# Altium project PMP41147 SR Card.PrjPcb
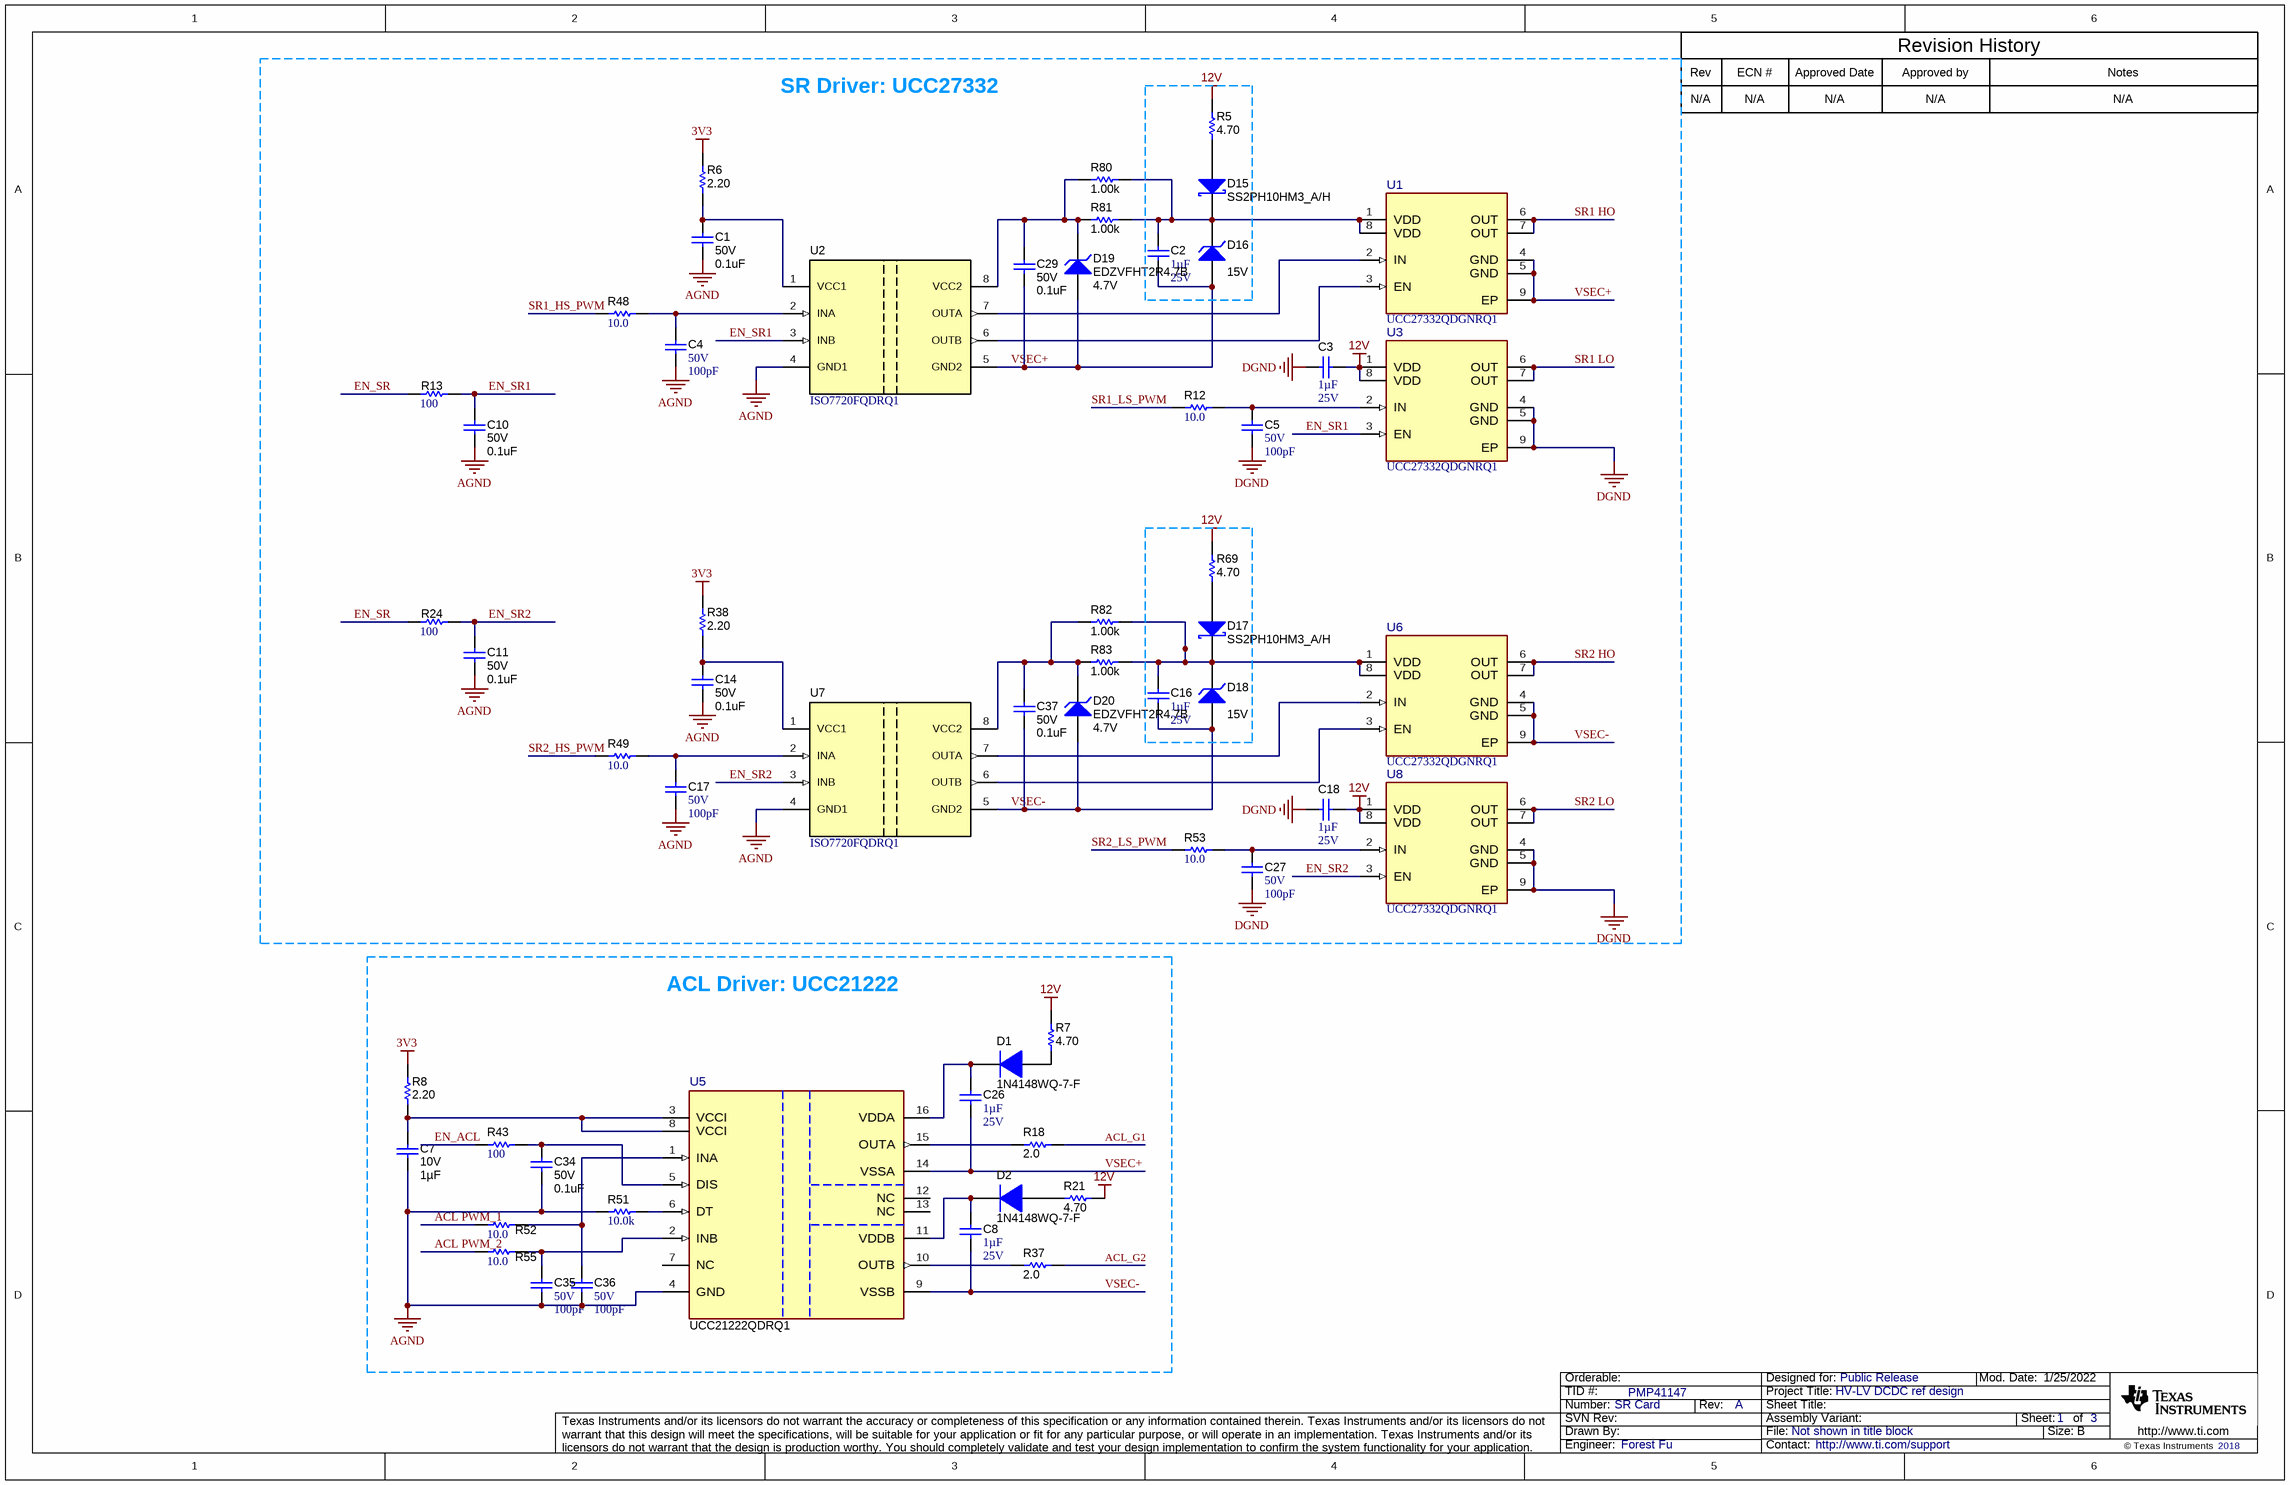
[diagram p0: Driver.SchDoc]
CopyrightYear: 2018; PCB_Layout: Forest Fu; PCB_Rev: A; PRJ_Customer: Public Release; PRJ_Engineer: Forest Fu; PRJ_Number: SR Card; PRJ_Title: HV-LV DCDC ref design; SCH_Rev: A; TechSupport: http://www.ti.com/support; TID: PMP41147
3 sheets, 165 parts. Net scope: global (net labels, ports and power ports of the same name join across sheets).
Board file: SR Card.PcbDoc
Sheets:
  Driver.SchDoc
  Power Stage.SchDoc
  SR Card_Hardware.SchDoc

## Sheet Driver.SchDoc
size 431 x 279 mm; Date: Not shown in title block; ApprovedBy: Not shown in title block; CheckedBy: Not shown in title block; Author: Not shown in title block; CompanyName: Not shown in title block; Engineer: Not shown in title block; Organization: Not shown in title block; Address1: Not shown in title block; Address2: Not shown in title block; Address3: Not shown in title block; Address4: Not shown in title block; DocumentNumber: 1; Revision: Use project parameter SCH_Rev; SheetNumber: 1; SheetTotal: 3; PageSetup: Record=PageOptions¦CenterHorizontal=True¦CenterVertical=True¦PrintScale=1.00¦XCorrection=1.00¦YCorrection=1.00¦PrintKind=0¦BorderSize=5000000¦LeftOffset=0¦BottomOffset=0¦Orientation=2¦PaperLength=1000¦PaperWidth=1000¦Scale=100¦PaperSource=15¦PrintQuality=600¦MediaType=1¦DitherType=10¦PaperKind=Letter¦PrintScaleMode=1

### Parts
C1  VDC_V: 50V  ValueDisplayed: 0.1uF  [0402]  (hidden comment: GCM155R71H104KE02D)
C2  Cap_F: 1µF  VDC_V: 25V  [0603]  (hidden comment: CGA3E1X7R1E105M080AC)
C3  Cap_F: 1µF  VDC_V: 25V  [0603]  (hidden comment: CGA3E1X7R1E105M080AC)
C4  VDC_V: 50V  ValueDisplayed: 100pF  [0402]  (hidden comment: CC0402KRX7R9BB101)
C5  VDC_V: 50V  ValueDisplayed: 100pF  [0402]  (hidden comment: CC0402KRX7R9BB101)
C7  VDC_V: 10V  ValueDisplayed: 1µF  [0402]  (hidden comment: GRT155C71A105KE13D)
C8  Cap_F: 1µF  VDC_V: 25V  [0603]  (hidden comment: CGA3E1X7R1E105M080AC)
C10  VDC_V: 50V  ValueDisplayed: 0.1uF  [0402]  (hidden comment: GCM155R71H104KE02D)
C11  VDC_V: 50V  ValueDisplayed: 0.1uF  [0402]  (hidden comment: GCM155R71H104KE02D)
C14  VDC_V: 50V  ValueDisplayed: 0.1uF  [0402]  (hidden comment: GCM155R71H104KE02D)
C16  Cap_F: 1µF  VDC_V: 25V  [0603]  (hidden comment: CGA3E1X7R1E105M080AC)
C17  VDC_V: 50V  ValueDisplayed: 100pF  [0402]  (hidden comment: CC0402KRX7R9BB101)
C18  Cap_F: 1µF  VDC_V: 25V  [0603]  (hidden comment: CGA3E1X7R1E105M080AC)
C26  Cap_F: 1µF  VDC_V: 25V  [0603]  (hidden comment: CGA3E1X7R1E105M080AC)
C27  VDC_V: 50V  ValueDisplayed: 100pF  [0402]  (hidden comment: CC0402KRX7R9BB101)
C29  VDC_V: 50V  ValueDisplayed: 0.1uF  [0402]  (hidden comment: GCM155R71H104KE02D)
C34  VDC_V: 50V  ValueDisplayed: 0.1uF  [0402]  (hidden comment: GCM155R71H104KE02D)
C35  VDC_V: 50V  ValueDisplayed: 100pF  [0402]  (hidden comment: CC0402KRX7R9BB101)
C36  VDC_V: 50V  ValueDisplayed: 100pF  [0402]  (hidden comment: CC0402KRX7R9BB101)
C37  VDC_V: 50V  ValueDisplayed: 0.1uF  [0402]  (hidden comment: GCM155R71H104KE02D)
D1  1N4148WQ-7-F  [SOD-123]
D2  1N4148WQ-7-F  [SOD-123]
D15  SS2PH10HM3_A/H  [DO-220AA]
D16  value 15V  [SOD-323]  (hidden comment: SZMM3Z15VST1G)
D17  SS2PH10HM3_A/H  [DO-220AA]
D18  value 15V  [SOD-323]  (hidden comment: SZMM3Z15VST1G)
D19  EDZVFHT2R4.7B  value 4.7V  [SOD-523]
D20  EDZVFHT2R4.7B  value 4.7V  [SOD-523]
R5  ValueDisplayed: 4.70  [0805_HV]  (hidden comment: CRCW08054R70FKEAHP)
R6  ValueDisplayed: 2.20  [0402]  (hidden comment: RL0510S-2R2-F)
R7  ValueDisplayed: 4.70  [0805_HV]  (hidden comment: CRCW08054R70FKEAHP)
R8  ValueDisplayed: 2.20  [0402]  (hidden comment: RL0510S-2R2-F)
R12  ValueDisplayed: 10.0  [0402]  (hidden comment: RMCF0402JT10R0)
R13  ValueDisplayed: 100  [0402]  (hidden comment: CRCW0402100RFKED)
R18  ValueDisplayed: 2.0  [0603]  (hidden comment: CRCW06032R00JNEA)
R21  ValueDisplayed: 4.70  [0805_HV]  (hidden comment: CRCW08054R70FKEAHP)
R24  ValueDisplayed: 100  [0402]  (hidden comment: CRCW0402100RFKED)
R37  ValueDisplayed: 2.0  [0603]  (hidden comment: CRCW06032R00JNEA)
R38  ValueDisplayed: 2.20  [0402]  (hidden comment: RL0510S-2R2-F)
R43  ValueDisplayed: 100  [0402]  (hidden comment: CRCW0402100RFKED)
R48  ValueDisplayed: 10.0  [0402]  (hidden comment: RMCF0402JT10R0)
R49  ValueDisplayed: 10.0  [0402]  (hidden comment: RMCF0402JT10R0)
R51  ValueDisplayed: 10.0k  [0402]  (hidden comment: ERJPA2F1002X)
R52  ValueDisplayed: 10.0  [0402]  (hidden comment: RMCF0402JT10R0)
R53  ValueDisplayed: 10.0  [0402]  (hidden comment: RMCF0402JT10R0)
R55  ValueDisplayed: 10.0  [0402]  (hidden comment: RMCF0402JT10R0)
R69  ValueDisplayed: 4.70  [0805_HV]  (hidden comment: CRCW08054R70FKEAHP)
R80  ValueDisplayed: 1.00k  [0402]  (hidden comment: ERA-2APB102X)
R81  ValueDisplayed: 1.00k  [0402]  (hidden comment: ERA-2APB102X)
R82  ValueDisplayed: 1.00k  [0402]  (hidden comment: ERA-2APB102X)
R83  ValueDisplayed: 1.00k  [0402]  (hidden comment: ERA-2APB102X)
U1  UCC27332QDGNRQ1  [DGN0008G-MFG]
U2  ISO7720FQDRQ1  [D0008A_N]
U3  UCC27332QDGNRQ1  [DGN0008G-MFG]
U5  UCC21222QDRQ1  [D0016B-MFG]
U6  UCC27332QDGNRQ1  [DGN0008G-MFG]
U7  ISO7720FQDRQ1  [D0008A_N]
U8  UCC27332QDGNRQ1  [DGN0008G-MFG]

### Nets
3V3: R6.2 R8.2 R38.2
12V: C3.1 C18.1 R5.2 R7.2 R21.1 R69.2 U3.1(VDD) U3.8(VDD) U8.1(VDD) U8.8(VDD)
AGND: C1.2 C4.1 C7.2 C10.2 C11.2 C14.2 C17.1 C34.2 C35.2 C36.2 R51.2 U2.4(GND1) U5.4(GND) U7.4(GND1)
DGND: C3.2 C5.2 C18.2 C27.2 U3.4(GND) U3.5(GND) U3.9(EP) U8.4(GND) U8.5(GND) U8.9(EP)
ACL PWM_1: R52.1
ACL PWM_2: R55.1
ACL_G1: R18.2
ACL_G2: R37.2
EN_ACL: R43.1
EN_SR: R13.1 R24.1
EN_SR1: C10.1 R13.2 U2.3(INB) U3.3(EN)
EN_SR2: C11.1 R24.2 U7.3(INB) U8.3(EN)
SR1 HO: U1.6(OUT) U1.7(OUT)
SR1 LO: U3.6(OUT) U3.7(OUT)
SR1_HS_PWM: R48.1
SR1_LS_PWM: R12.1
SR2 HO: U6.6(OUT) U6.7(OUT)
SR2 LO: U8.6(OUT) U8.7(OUT)
SR2_HS_PWM: R49.1
SR2_LS_PWM: R53.1
VSEC+: C2.2 C26.2 C29.2 D16.2(A) D19.2(A) U1.4(GND) U1.5(GND) U1.9(EP) U2.5(GND2) U5.14(VSSA)
VSEC-: C8.2 C16.2 C37.2 D18.2(A) D20.2(A) U5.9(VSSB) U6.4(GND) U6.5(GND) U6.9(EP) U7.5(GND2)
NetC1_1: C1.1 R6.1 U2.1(VCC1)
NetC2_1: C2.1 D15.1(K) D16.1(K) R80.2 R81.2 U1.1(VDD) U1.8(VDD)
NetC4_2: C4.2 R48.2 U2.2(INA)
NetC5_1: C5.1 R12.2 U3.2(IN)
NetC7_1: C7.1 R8.1 U5.3(VCCI) U5.8(VCCI)
NetC8_1: C8.1 D2.1(K) U5.11(VDDB)
NetC14_1: C14.1 R38.1 U7.1(VCC1)
NetC16_1: C16.1 D17.1(K) D18.1(K) R82.2 R83.2 U6.1(VDD) U6.8(VDD)
NetC17_2: C17.2 R49.2 U7.2(INA)
NetC26_1: C26.1 D1.1(K) U5.16(VDDA)
NetC27_1: C27.1 R53.2 U8.2(IN)
NetC29_1: C29.1 D19.1(K) R80.1 R81.1 U2.8(VCC2)
NetC34_1: C34.1 R43.2 U5.5(DIS)
NetC35_1: C35.1 R55.2 U5.2(INB)
NetC36_1: C36.1 R52.2 U5.1(INA)
NetC37_1: C37.1 D20.1(K) R82.1 R83.1 U7.8(VCC2)
NetD1_2: D1.2(A) R7.1
NetD2_2: D2.2(A) R21.2
NetD15_2: D15.2(A) R5.1
NetD17_2: D17.2(A) R69.1
NetR18_1: R18.1 U5.15(OUTA)
NetR37_1: R37.1 U5.10(OUTB)
NetR51_1: R51.1 U5.6(DT)
NetU1_2: U1.2(IN) U2.7(OUTA)
NetU1_3: U1.3(EN) U2.6(OUTB)
NetU6_2: U6.2(IN) U7.7(OUTA)
NetU6_3: U6.3(EN) U7.6(OUTB)

Not connected (* = marked no-connect by the designer): U5 7(NC) 12(NC) 13(NC)

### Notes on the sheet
- SR Driver: UCC27332
- Rev
- N/A
- ECN #
- Approved Date
- Approved by
- Revision History
- Notes
- ACL Driver: UCC21222

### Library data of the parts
C1 C10 C11 C14 C29 C34 C37 = CMP-0006356-1: CAP, CERM, 0.1 uF, 50 V, +/- 10%, X7R, AEC-Q200 Grade 1, 0402; Manufacturer: MuRata; TaMin_C: -55°C; Polarized: N; SizeAreaWB_mm2: 3; Value1: Unknown; U/M: EA; Value: 0.1uF; TaMax_C: 125°C; SizeZ_mm: 0.6; SizeX_mm: 1; SizeY_mm: 0.5; AEC Qualified: Y; Cap_F: 100nF; AEC Category: Q200
C2 C3 C8 C16 C18 C26 = CMP-0082113-1: CAP, CERM, 1 µF, 25 V,+/- 20%, X7R, AEC-Q200 Grade 1, 0603; Manufacturer: TDK; SizeAreaWB_mm2: 4.68; SizeArea_mm2: 1.28; AEC Qualified: Y; AEC Category: Q200; Value: 1uF; TaMax_C: 125°C; SizeZ_mm: 1; Polarized: N; TaMin_C: -55°C; SizeY_mm: 0.8; U/M: EA; SizeX_mm: 1.6
C4 C5 C17 C27 C35 C36 = CMP-0006305-2: CAP, CERM, 100 pF, 50 V, +/- 10%, X7R, 0402; Manufacturer: Yageo America; TaMin_C: -55°C; Polarized: N; SizeAreaWB_mm2: 3; Value1: Unknown; U/M: EA; Value: 100pF; TaMax_C: 125°C; SizeZ_mm: 0.6; SizeX_mm: 1; SizeY_mm: 0.5; AEC Category: Q200
C7 = CMP-0085818-1: CAP, CERM, 1 µF, 10 V,+/- 10%, X7S, AEC-Q200 Grade 1, 0402; Manufacturer: MuRata; Value: 1uF; SizeX_mm: 1; TaMax_C: 125°C; SizeArea_mm2: 0.5; SizeZ_mm: 0.6; AEC Category: Q200; Polarized: N; SizeAreaWB_mm2: 3; TaMin_C: -55°C; AEC Qualified: Y; U/M: EA
D1 D2 = CMP-0750148-1: Diode, Switching, 100 V, 0.3 A, AEC-Q101, SOD-123; Manufacturer: Diodes Inc.; Value2: 1.25V; TJmax_C: 150°C; AEC Category: Q101; Value: 100V; SizeAreaWB_mm2: 13.095; SizeArea_mm2: 6.545; SizeX_mm: 3.85; AEC Qualified: Y; Io_A: 300mA; Value1: 0.3A; SizeZ_mm: 1.35; SizeY_mm: 1.7
D15 D17 = CMP-0028941-1: Diode, Schottky, 100 V, 2 A, AEC-Q101, DO-220AA; Manufacturer: Vishay-Semiconductor; Io_A: 2A; Green_Lifecycle: Not Set; SizeAreaWB_mm2: 14.3925; Vr_V: 100V; Green_REACh: Incomplete; TJmax_C: 175°C; U/M: EA; Value: 100V; SizeZ_mm: 1.15; SizeX_mm: 3.75; SizeY_mm: 2.03; Vf_V: 770mV; Value2: 0.77V; SizeArea_mm2: 7.6125; AEC Qualified: Y; AEC Category: Q101
D16 D18 = CMP-0085761-1: Diode, Zener, 15 V, 300 mW, AEC-Q101, SOD-323; Manufacturer: ON Semiconductor; Value1: 0.3W; Power_W: 300mW; SizeAreaWB_mm2: 8.695; AEC Category: Q101; SizeArea_mm2: 3.645; RJA_CperW: 416; SizeY_mm: 1.35; SizeX_mm: 2.7; AEC Qualified: Y; SizeZ_mm: 1
D19 D20 = CMP-0005910-2: Diode, Zener, 4.7 V, 150 mW, AEC-Q101, SOD-523; Manufacturer: Rohm; Power_W: 150mW; SizeAreaWB_mm2: 5.13; Value1: 0.15W; U/M: EA; SizeZ_mm: 0.65; SizeX_mm: 1.7; SizeY_mm: 0.9; SizeArea_mm2: 1.53; AEC Qualified: Y; AEC Category: Q101
R5 R7 R21 R69 = CMP-0021312-3: RES, 4.70, 1%, 0.5 W, AEC-Q200 Grade 0, 0805; Manufacturer: Vishay-Dale; Power_W: 500mW; TempCo: 100 ppm/C; Value_Code: 4R70; Value: 4.70; Res_ohm: 4.7; SizeX_mm: 2; SizeY_mm: 1.25; SizeZ_mm: 1.45; Value2: 0.5W; SizeArea_mm2: 2.5; AEC Qualified: Y; AEC Grade: 0; AEC Category: Q200; VDC_V: 150V
R6 R8 R38 = CMP-0082064-1: RES, 2.20, 1%, 0.167 W, AEC-Q200 Grade 0, 0402; Manufacturer: Susumu Co Ltd; Value_Code: 2R20; SizeAreaWB_mm2: 3; SizeArea_mm2: 0.5; AEC Qualified: Y; AEC Category: Q200; Res_ohm: 2.2; Value: 2.20; SizeZ_mm: 0.6; TempCo: 200 ppm/C; AEC Grade: 0; Power_W: 167mW; Value2: 0.167W; SizeX_mm: 1
R12 R48 R49 R52 R53 R55 = CMP-0026764-1: RES, 10.0, 1%, 0.063 W, AEC-Q200 Grade 0, 0402; Manufacturer: Stackpole Electronics Inc; Power_W: 63mW; TempCo: 100 ppm/C; Value_Code: 10R0; U/M: EA; Value: 10.0; EIA_Code: E96; Res_ohm: 10; SizeX_mm: 1; SizeY_mm: 0.5; SizeZ_mm: 0.6; Value2: 0.063W; AEC Qualified: Y; AEC Grade: 0; AEC Category: Q200
R13 R24 R43 = CMP-0025951-3: RES, 100, 1%, 0.063 W, AEC-Q200 Grade 0, 0402; Manufacturer: Vishay-Dale; Power_W: 63mW; TempCo: 100 ppm/C; Value_Code: 100R; Value: 100; EIA_Code: E96; SizeX_mm: 1; SizeY_mm: 0.5; SizeZ_mm: 0.6; Value2: 0.063W; AEC Qualified: Y; VDC_V: 50V; AEC Category: Q200; AEC Grade: 0
R18 R37 = CMP-0025776-4: RES, 2.0, 5%, 0.1 W, AEC-Q200 Grade 0, 0603; Manufacturer: Vishay-Dale; Power_W: 100mW; TempCo: 200 ppm/C; Value_Code: 2R00; Value: 2.0; EIA_Code: E24; Res_ohm: 2; SizeX_mm: 1.6; SizeY_mm: 0.8; SizeZ_mm: 1; Value2: 0.1W; SizeArea_mm2: 1.28; AEC Qualified: Y; VDC_V: 75V; AEC Category: Q200; AEC Grade: 0
R51 = CMP-0078779-1: RES, 10.0 k, 1%, 0.2 W, AEC-Q200 Grade 0, 0402; Manufacturer: Panasonic; Value_Code: 10k0; SizeArea_mm2: 0.5; AEC Qualified: Y; AEC Category: Q200; Res_ohm: 10k; Value: 10.0k; SizeZ_mm: 0.6; EIA_Code: E96; TempCo: 100 ppm/C; AEC Grade: 0; Power_W: 200mW; VDC_V: 50V; Value2: 0.2W; SizeX_mm: 1
R80-R83 = CMP-0026790-1: RES, 1.00 k, 0.1%, 0.063 W, AEC-Q200 Grade 0, 0402; Manufacturer: Panasonic; Power_W: 63mW; TempCo: 15 ppm/C; Value_Code: 1k00; U/M: EA; Value: 1.00k; EIA_Code: E192; Res_ohm: 1k; SizeX_mm: 1; SizeY_mm: 0.5; SizeZ_mm: 0.6; Value2: 0.063W; AEC Qualified: Y; VDC_V: 50V; AEC Grade: 0; AEC Category: Q200
U1 U3 U6 U8 = CMP-0095529-1: Single 9-A High Speed Low-Side MOSFET Driver W Enable; Manufacturer: Texas Instruments; SizeZ_mm: 1.1mm; Number Of Outputs: 1; AEC Qualified: Unknown; Min Supply Voltage: 4V; Max Supply Voltage: 18V; Standoff Height: 0.05mm
U2 U7 = CMP-0860111-1: Automotive, High Speed, Robust EMC Reinforced Dual-Channel Digital Isolator, D0008A (SOIC-8); Manufacturer: Texas Instruments; SizeZ_mm: 1.75; CompType: IC; SizeArea_mm2: 30.38; SizeAreaWB_mm2: 56.58; AEC Qualified: Y; SizeX_mm: 4.9; SizeY_mm: 6.2; AEC Category: Q200
U5 = CMP-0090594-2: Half-Bridge Gate Driver IC CMOS/TTL 16-SOIC; Manufacturer: Texas Instruments; TaMin_C: -40°C; AEC Category: Q200; Turn On Delay Time: 28ns; Nominal Supply Current: 1-2.5mA; Max Power Dissipation: 1825mW; TJmax_C: +150°C; SizeZ_mm: 1.75mm; TaMax_C: +125°C; Fall Time: 6ns; Output Voltage: 9.2-18V; Standoff Height: 0.1mm; AEC Qualified: Yes; Rise Time: 5ns; Max Supply Voltage: 5.5V; Number Of Outputs: 2; AEC Grade: Grade 1; Propagation Delay: 25ns; Min Supply Voltage: 3V

## Sheet Power Stage.SchDoc
size 431 x 279 mm; Date: Not shown in title block; ApprovedBy: Not shown in title block; CheckedBy: Not shown in title block; Author: Not shown in title block; CompanyName: Not shown in title block; Engineer: Not shown in title block; Organization: Not shown in title block; Address1: Not shown in title block; Address2: Not shown in title block; Address3: Not shown in title block; Address4: Not shown in title block; DocumentNumber: 2; Revision: Use project parameter SCH_Rev; SheetNumber: 2; SheetTotal: 3; PageSetup: Record=PageOptions¦CenterHorizontal=True¦CenterVertical=True¦PrintScale=1.00¦XCorrection=1.00¦YCorrection=1.00¦PrintKind=0¦BorderSize=5000000¦LeftOffset=0¦BottomOffset=0¦Orientation=2¦PaperLength=1000¦PaperWidth=1000¦Scale=100¦PaperSource=15¦PrintQuality=600¦MediaType=1¦DitherType=10¦PaperKind=Letter¦PrintScaleMode=1
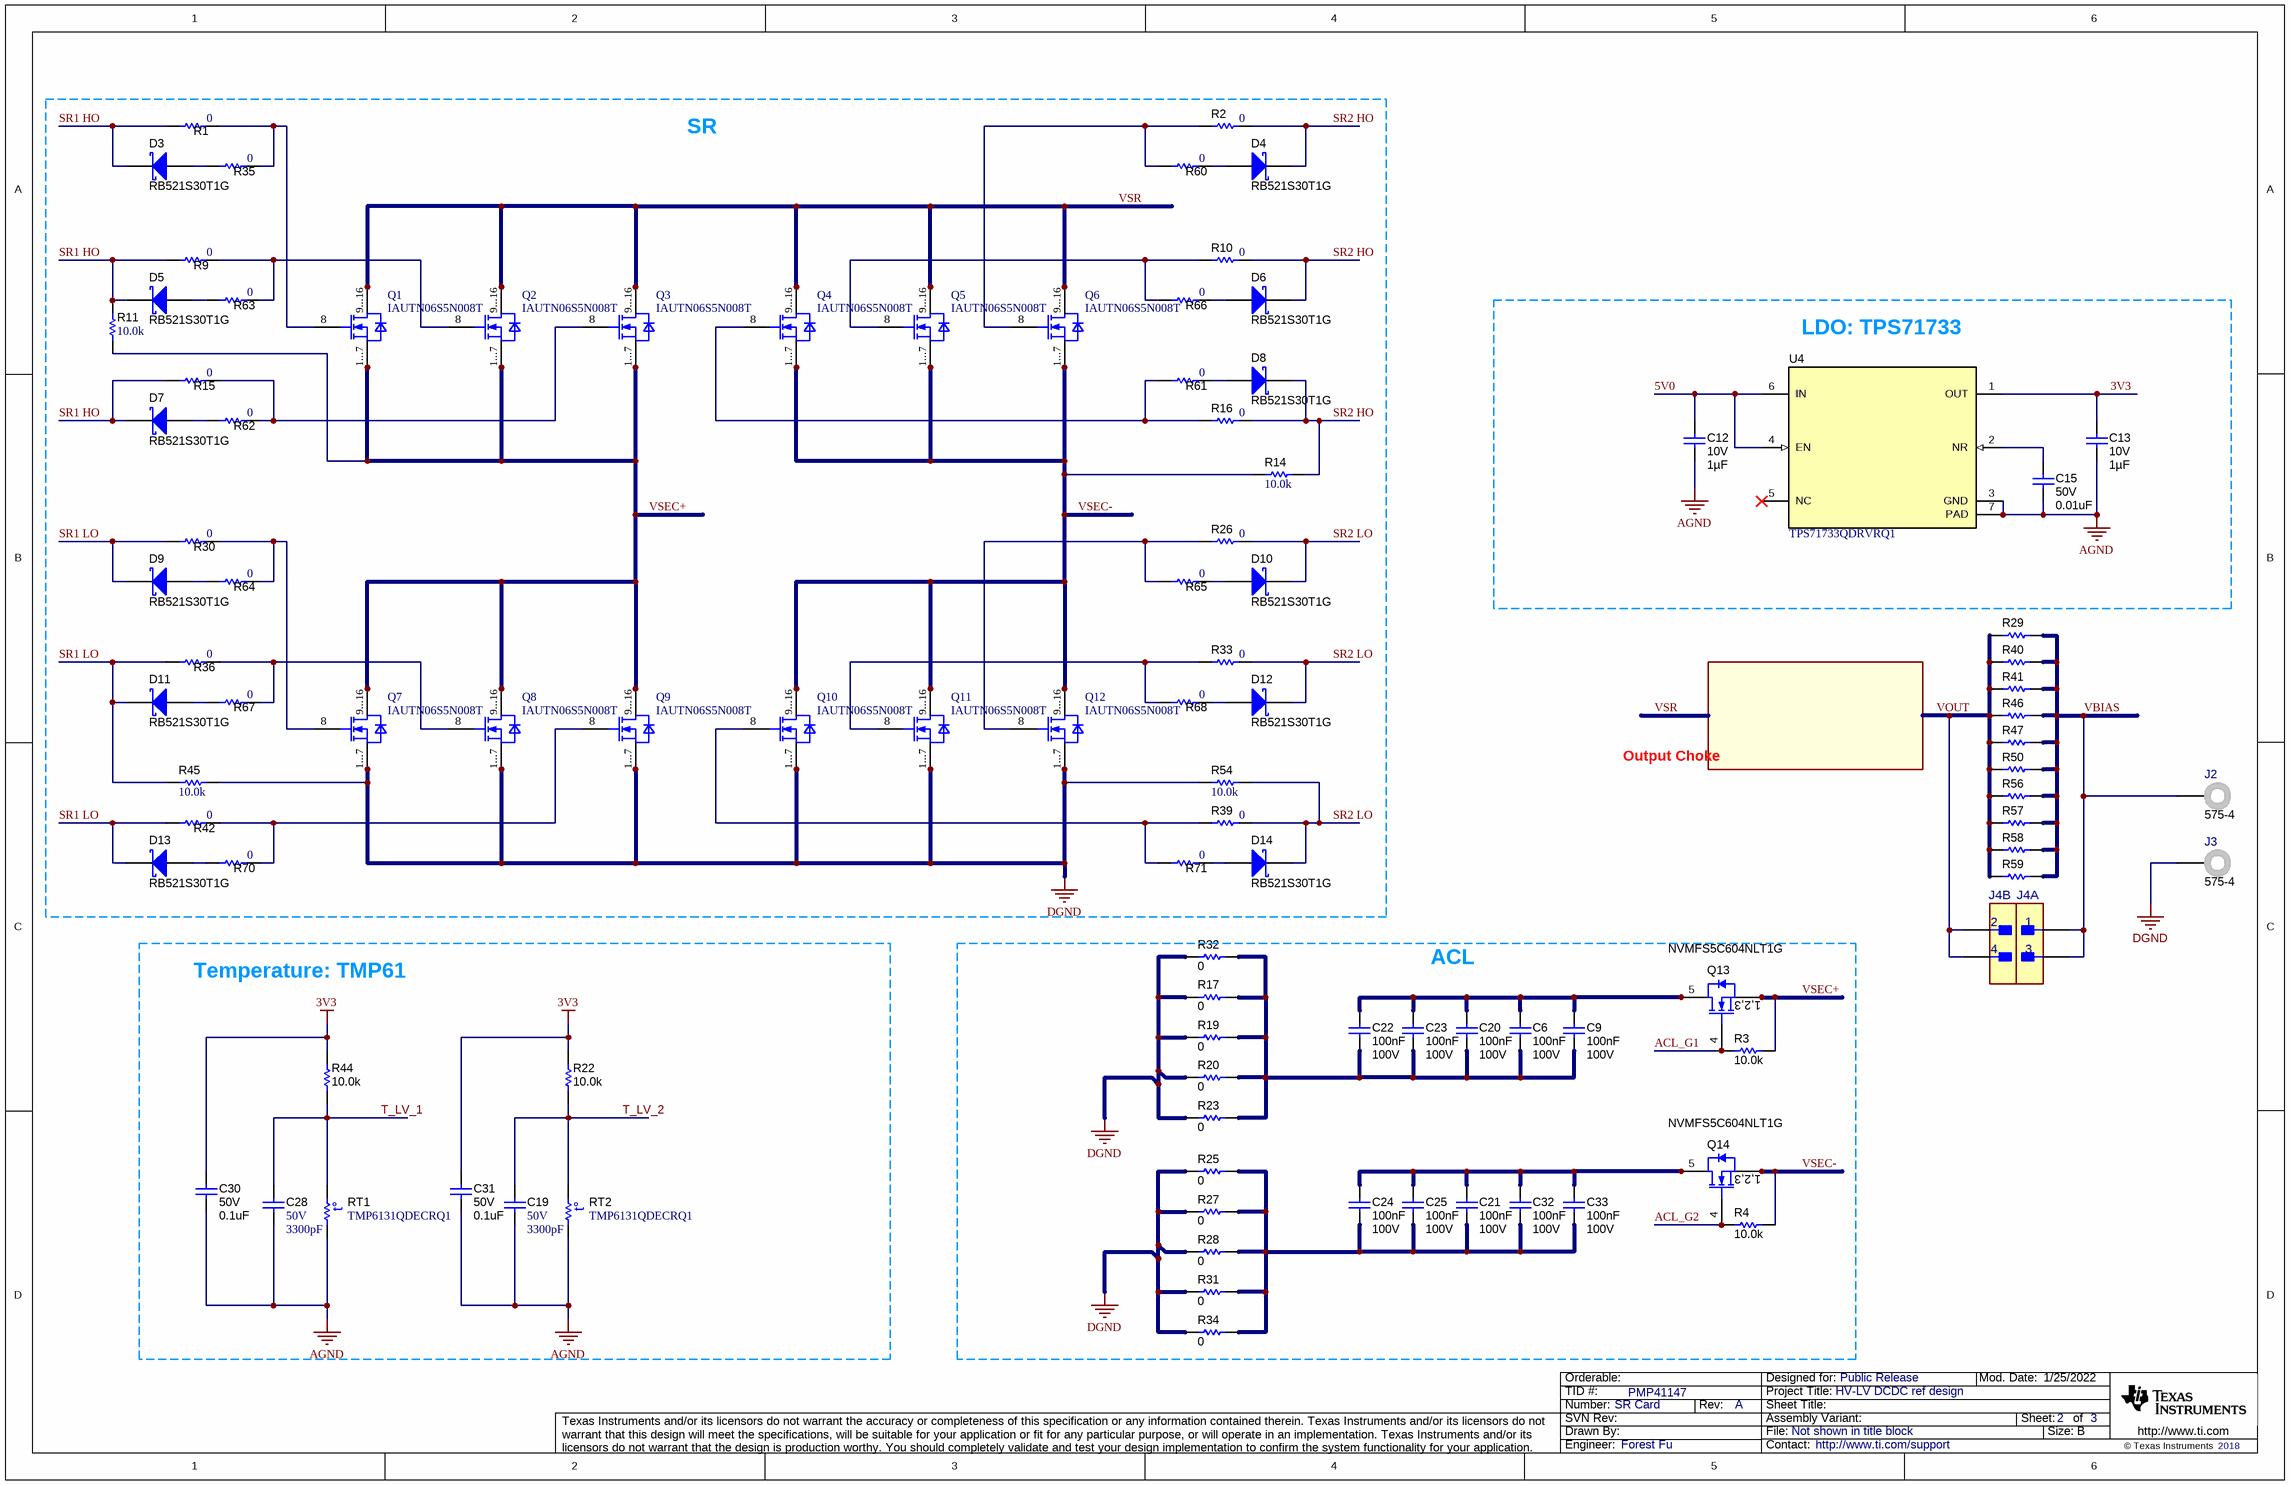
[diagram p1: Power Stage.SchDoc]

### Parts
C6  Cap_F: 100nF  VDC_V: 100V  [0805_HV]  (hidden comment: GCM21BR72A104KA37L)
C9  Cap_F: 100nF  VDC_V: 100V  [0805_HV]  (hidden comment: GCM21BR72A104KA37L)
C12  VDC_V: 10V  ValueDisplayed: 1µF  [0402]  (hidden comment: GRT155C71A105KE13D)
C13  VDC_V: 10V  ValueDisplayed: 1µF  [0402]  (hidden comment: GRT155C71A105KE13D)
C15  VDC_V: 50V  ValueDisplayed: 0.01uF  [0402]  (hidden comment: CGA2B3X7R1H103K050BB)
C19  VDC_V: 50V  ValueDisplayed: 3300pF  [0402]  (hidden comment: CGA2B2X7R1H332K050BA)
C20  Cap_F: 100nF  VDC_V: 100V  [0805_HV]  (hidden comment: GCM21BR72A104KA37L)
C21  Cap_F: 100nF  VDC_V: 100V  [0805_HV]  (hidden comment: GCM21BR72A104KA37L)
C22  Cap_F: 100nF  VDC_V: 100V  [0805_HV]  (hidden comment: GCM21BR72A104KA37L)
C23  Cap_F: 100nF  VDC_V: 100V  [0805_HV]  (hidden comment: GCM21BR72A104KA37L)
C24  Cap_F: 100nF  VDC_V: 100V  [0805_HV]  (hidden comment: GCM21BR72A104KA37L)
C25  Cap_F: 100nF  VDC_V: 100V  [0805_HV]  (hidden comment: GCM21BR72A104KA37L)
C28  VDC_V: 50V  ValueDisplayed: 3300pF  [0402]  (hidden comment: CGA2B2X7R1H332K050BA)
C30  VDC_V: 50V  ValueDisplayed: 0.1uF  [0402]  (hidden comment: GCM155R71H104KE02D)
C31  VDC_V: 50V  ValueDisplayed: 0.1uF  [0402]  (hidden comment: GCM155R71H104KE02D)
C32  Cap_F: 100nF  VDC_V: 100V  [0805_HV]  (hidden comment: GCM21BR72A104KA37L)
C33  Cap_F: 100nF  VDC_V: 100V  [0805_HV]  (hidden comment: GCM21BR72A104KA37L)
D3  RB521S30T1G  [SOD-523]
D4  RB521S30T1G  [SOD-523]
D5  RB521S30T1G  [SOD-523]
D6  RB521S30T1G  [SOD-523]
D7  RB521S30T1G  [SOD-523]
D8  RB521S30T1G  [SOD-523]
D9  RB521S30T1G  [SOD-523]
D10  RB521S30T1G  [SOD-523]
D11  RB521S30T1G  [SOD-523]
D12  RB521S30T1G  [SOD-523]
D13  RB521S30T1G  [SOD-523]
D14  RB521S30T1G  [SOD-523]
J2  575-4  [Keystone_575-4]
J3  575-4  [Keystone_575-4]
J4  FTSH-102-01-L-D-RA  [FP-FTSH-102-01-L-D-RA_HDR4-MFG]  (value not drawn)  (parts A,B of 2)
Q1  IAUTN06S5N008T  [SOIC120P1500X235-16N-1-V]
Q2  IAUTN06S5N008T  [SOIC120P1500X235-16N-1-V]
Q3  IAUTN06S5N008T  [SOIC120P1500X235-16N-1-V]
Q4  IAUTN06S5N008T  [SOIC120P1500X235-16N-1-V]
Q5  IAUTN06S5N008T  [SOIC120P1500X235-16N-1-V]
Q6  IAUTN06S5N008T  [SOIC120P1500X235-16N-1-V]
Q7  IAUTN06S5N008T  [SOIC120P1500X235-16N-1-V]
Q8  IAUTN06S5N008T  [SOIC120P1500X235-16N-1-V]
Q9  IAUTN06S5N008T  [SOIC120P1500X235-16N-1-V]
Q10  IAUTN06S5N008T  [SOIC120P1500X235-16N-1-V]
Q11  IAUTN06S5N008T  [SOIC120P1500X235-16N-1-V]
Q12  IAUTN06S5N008T  [SOIC120P1500X235-16N-1-V]
Q13  NVMFS5C604NLT1G  [TRANS_DFN5]
Q14  NVMFS5C604NLT1G  [TRANS_DFN5]
R1  ValueDisplayed: 0  [0402]  (hidden comment: CRCW04020000Z0EDHP)
R2  ValueDisplayed: 0  [0402]  (hidden comment: CRCW04020000Z0EDHP)
R3  ValueDisplayed: 10.0k  [0402]  (hidden comment: RMCF0402FT10K0)
R4  ValueDisplayed: 10.0k  [0402]  (hidden comment: RMCF0402FT10K0)
R9  ValueDisplayed: 0  [0402]  (hidden comment: CRCW04020000Z0EDHP)
R10  ValueDisplayed: 0  [0402]  (hidden comment: CRCW04020000Z0EDHP)
R11  ValueDisplayed: 10.0k  [0402]  (hidden comment: ERJPA2F1002X)
R14  ValueDisplayed: 10.0k  [0402]  (hidden comment: ERJPA2F1002X)
R15  ValueDisplayed: 0  [0402]  (hidden comment: CRCW04020000Z0EDHP)
R16  ValueDisplayed: 0  [0402]  (hidden comment: CRCW04020000Z0EDHP)
R17  ValueDisplayed: 0  [0805_HV]  (hidden comment: CRCW08050000Z0EA)
R19  ValueDisplayed: 0  [0805_HV]  (hidden comment: CRCW08050000Z0EA)
R20  ValueDisplayed: 0  [0805_HV]  (hidden comment: CRCW08050000Z0EA)
R22  ValueDisplayed: 10.0k  [0402]  (hidden comment: RMCF0402FT10K0)
R23  ValueDisplayed: 0  [0805_HV]  (hidden comment: CRCW08050000Z0EA)
R25  ValueDisplayed: 0  [0805_HV]  (hidden comment: CRCW08050000Z0EA)
R26  ValueDisplayed: 0  [0402]  (hidden comment: CRCW04020000Z0EDHP)
R27  ValueDisplayed: 0  [0805_HV]  (hidden comment: CRCW08050000Z0EA)
R28  ValueDisplayed: 0  [0805_HV]  (hidden comment: CRCW08050000Z0EA)
R29  LR12FTDR0M50  [2512]  (value not drawn)
R30  ValueDisplayed: 0  [0402]  (hidden comment: CRCW04020000Z0EDHP)
R31  ValueDisplayed: 0  [0805_HV]  (hidden comment: CRCW08050000Z0EA)
R32  ValueDisplayed: 0  [0805_HV]  (hidden comment: CRCW08050000Z0EA)
R33  ValueDisplayed: 0  [0402]  (hidden comment: CRCW04020000Z0EDHP)
R34  ValueDisplayed: 0  [0805_HV]  (hidden comment: CRCW08050000Z0EA)
R35  ValueDisplayed: 0  [0402]  (hidden comment: CRCW04020000Z0EDHP)
R36  ValueDisplayed: 0  [0402]  (hidden comment: CRCW04020000Z0EDHP)
R39  ValueDisplayed: 0  [0402]  (hidden comment: CRCW04020000Z0EDHP)
R40  LR12FTDR0M50  [2512]  (value not drawn)
R41  LR12FTDR0M50  [2512]  (value not drawn)
R42  ValueDisplayed: 0  [0402]  (hidden comment: CRCW04020000Z0EDHP)
R44  ValueDisplayed: 10.0k  [0402]  (hidden comment: RMCF0402FT10K0)
R45  ValueDisplayed: 10.0k  [0402]  (hidden comment: ERJPA2F1002X)
R46  LR12FTDR0M50  [2512]  (value not drawn)
R47  LR12FTDR0M50  [2512]  (value not drawn)
R50  LR12FTDR0M50  [2512]  (value not drawn)
R54  ValueDisplayed: 10.0k  [0402]  (hidden comment: ERJPA2F1002X)
R56  LR12FTDR0M50  [2512]  (value not drawn)
R57  LR12FTDR0M50  [2512]  (value not drawn)
R58  LR12FTDR0M50  [2512]  (value not drawn)
R59  LR12FTDR0M50  [2512]  (value not drawn)
R60  ValueDisplayed: 0  [0402]  (hidden comment: CRCW04020000Z0EDHP)
R61  ValueDisplayed: 0  [0402]  (hidden comment: CRCW04020000Z0EDHP)
R62  ValueDisplayed: 0  [0402]  (hidden comment: CRCW04020000Z0EDHP)
R63  ValueDisplayed: 0  [0402]  (hidden comment: CRCW04020000Z0EDHP)
R64  ValueDisplayed: 0  [0402]  (hidden comment: CRCW04020000Z0EDHP)
R65  ValueDisplayed: 0  [0402]  (hidden comment: CRCW04020000Z0EDHP)
R66  ValueDisplayed: 0  [0402]  (hidden comment: CRCW04020000Z0EDHP)
R67  ValueDisplayed: 0  [0402]  (hidden comment: CRCW04020000Z0EDHP)
R68  ValueDisplayed: 0  [0402]  (hidden comment: CRCW04020000Z0EDHP)
R70  ValueDisplayed: 0  [0402]  (hidden comment: CRCW04020000Z0EDHP)
R71  ValueDisplayed: 0  [0402]  (hidden comment: CRCW04020000Z0EDHP)
RT1  TMP6131QDECRQ1  [DEC0002A-MFG]
RT2  TMP6131QDECRQ1  [DEC0002A-MFG]
U4  TPS71733QDRVRQ1  [DRV0006A]

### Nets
3V3: C13.1 C30.1 C31.1 R22.2 R44.2 U4.1(OUT)
AGND: C12.2 C13.2 C15.2 C19.2 C28.2 C30.2 C31.2 RT1.1 RT2.1 U4.3(GND) U4.7(PAD)
DGND: J3.1 Q7.1(SOURCE1) Q7.2(SOURCE2) Q7.3(SOURCE3) Q7.4(SOURCE4) Q7.5(SOURCE5) Q7.6(SOURCE6) Q7.7(SOURCE7) Q8.1(SOURCE1) Q8.2(SOURCE2) Q8.3(SOURCE3) Q8.4(SOURCE4) Q8.5(SOURCE5) Q8.6(SOURCE6) Q8.7(SOURCE7) Q9.1(SOURCE1) Q9.2(SOURCE2) Q9.3(SOURCE3) Q9.4(SOURCE4) Q9.5(SOURCE5) Q9.6(SOURCE6) Q9.7(SOURCE7) Q10.1(SOURCE1) Q10.2(SOURCE2) Q10.3(SOURCE3) Q10.4(SOURCE4) Q10.5(SOURCE5) Q10.6(SOURCE6) Q10.7(SOURCE7) Q11.1(SOURCE1) Q11.2(SOURCE2) Q11.3(SOURCE3) Q11.4(SOURCE4) Q11.5(SOURCE5) Q11.6(SOURCE6) Q11.7(SOURCE7) Q12.1(SOURCE1) Q12.2(SOURCE2) Q12.3(SOURCE3) Q12.4(SOURCE4) Q12.5(SOURCE5) Q12.6(SOURCE6) Q12.7(SOURCE7) R17.1 R19.1 R20.1 R23.1 R25.1 R27.1 R28.1 R31.1 R32.1 R34.1 R45.1 R54.2
5V0: C12.1 U4.4(EN) U4.6(IN)
ACL_G1: Q13.4(G) R3.2
ACL_G2: Q14.4(G) R4.2
SR1 HO: D3.1(K) D5.1(K) D7.1(K) R1.1 R9.1 R11.2 R15.1
SR1 LO: D9.1(K) D11.1(K) D13.1(K) R30.1 R36.1 R42.1 R45.2
SR2 HO: D4.1(K) D6.1(K) D8.1(K) R2.2 R10.2 R14.1 R16.2
SR2 LO: D10.1(K) D12.1(K) D14.1(K) R26.2 R33.2 R39.2 R54.1
T_LV_1: C28.1 R44.1 RT1.2
T_LV_2: C19.1 R22.1 RT2.2
VBIAS: J2.1 J4.1 J4.3 R29.2 R40.2 R41.2 R46.2 R47.2 R50.2 R56.2 R57.2 R58.2 R59.2
VOUT: J4.2 J4.4 R29.1 R40.1 R41.1 R46.1 R47.1 R50.1 R56.1 R57.1 R58.1 R59.1
VSEC+: Q1.1(SOURCE1) Q1.2(SOURCE2) Q1.3(SOURCE3) Q1.4(SOURCE4) Q1.5(SOURCE5) Q1.6(SOURCE6) Q1.7(SOURCE7) Q2.1(SOURCE1) Q2.2(SOURCE2) Q2.3(SOURCE3) Q2.4(SOURCE4) Q2.5(SOURCE5) Q2.6(SOURCE6) Q2.7(SOURCE7) Q3.1(SOURCE1) Q3.2(SOURCE2) Q3.3(SOURCE3) Q3.4(SOURCE4) Q3.5(SOURCE5) Q3.6(SOURCE6) Q3.7(SOURCE7) Q7.9(DRAIN1) Q7.10(DRAIN2) Q7.11(DRAIN3) Q7.12(DRAIN4) Q7.13(DRAIN5) Q7.14(DRAIN6) Q7.15(DRAIN7) Q7.16(DRAIN8) Q8.9(DRAIN1) Q8.10(DRAIN2) Q8.11(DRAIN3) Q8.12(DRAIN4) Q8.13(DRAIN5) Q8.14(DRAIN6) Q8.15(DRAIN7) Q8.16(DRAIN8) Q9.9(DRAIN1) Q9.10(DRAIN2) Q9.11(DRAIN3) Q9.12(DRAIN4) Q9.13(DRAIN5) Q9.14(DRAIN6) Q9.15(DRAIN7) Q9.16(DRAIN8) Q13.1(S) Q13.2(S) Q13.3(S) R3.1 R11.1
VSEC-: Q4.1(SOURCE1) Q4.2(SOURCE2) Q4.3(SOURCE3) Q4.4(SOURCE4) Q4.5(SOURCE5) Q4.6(SOURCE6) Q4.7(SOURCE7) Q5.1(SOURCE1) Q5.2(SOURCE2) Q5.3(SOURCE3) Q5.4(SOURCE4) Q5.5(SOURCE5) Q5.6(SOURCE6) Q5.7(SOURCE7) Q6.1(SOURCE1) Q6.2(SOURCE2) Q6.3(SOURCE3) Q6.4(SOURCE4) Q6.5(SOURCE5) Q6.6(SOURCE6) Q6.7(SOURCE7) Q10.9(DRAIN1) Q10.10(DRAIN2) Q10.11(DRAIN3) Q10.12(DRAIN4) Q10.13(DRAIN5) Q10.14(DRAIN6) Q10.15(DRAIN7) Q10.16(DRAIN8) Q11.9(DRAIN1) Q11.10(DRAIN2) Q11.11(DRAIN3) Q11.12(DRAIN4) Q11.13(DRAIN5) Q11.14(DRAIN6) Q11.15(DRAIN7) Q11.16(DRAIN8) Q12.9(DRAIN1) Q12.10(DRAIN2) Q12.11(DRAIN3) Q12.12(DRAIN4) Q12.13(DRAIN5) Q12.14(DRAIN6) Q12.15(DRAIN7) Q12.16(DRAIN8) Q14.1(S) Q14.2(S) Q14.3(S) R4.1 R14.2
VSR: Q1.9(DRAIN1) Q1.10(DRAIN2) Q1.11(DRAIN3) Q1.12(DRAIN4) Q1.13(DRAIN5) Q1.14(DRAIN6) Q1.15(DRAIN7) Q1.16(DRAIN8) Q2.9(DRAIN1) Q2.10(DRAIN2) Q2.11(DRAIN3) Q2.12(DRAIN4) Q2.13(DRAIN5) Q2.14(DRAIN6) Q2.15(DRAIN7) Q2.16(DRAIN8) Q3.9(DRAIN1) Q3.10(DRAIN2) Q3.11(DRAIN3) Q3.12(DRAIN4) Q3.13(DRAIN5) Q3.14(DRAIN6) Q3.15(DRAIN7) Q3.16(DRAIN8) Q4.9(DRAIN1) Q4.10(DRAIN2) Q4.11(DRAIN3) Q4.12(DRAIN4) Q4.13(DRAIN5) Q4.14(DRAIN6) Q4.15(DRAIN7) Q4.16(DRAIN8) Q5.9(DRAIN1) Q5.10(DRAIN2) Q5.11(DRAIN3) Q5.12(DRAIN4) Q5.13(DRAIN5) Q5.14(DRAIN6) Q5.15(DRAIN7) Q5.16(DRAIN8) Q6.9(DRAIN1) Q6.10(DRAIN2) Q6.11(DRAIN3) Q6.12(DRAIN4) Q6.13(DRAIN5) Q6.14(DRAIN6) Q6.15(DRAIN7) Q6.16(DRAIN8)
NetC6_1: C6.1 C9.1 C20.1 C22.1 C23.1 Q13.5(D) Q13.6(D)
NetC6_2: C6.2 C9.2 C20.2 C22.2 C23.2 R17.2 R19.2 R20.2 R23.2 R32.2
NetC15_1: C15.1 U4.2(NR)
NetC21_1: C21.1 C24.1 C25.1 C32.1 C33.1 Q14.5(D) Q14.6(D)
NetC21_2: C21.2 C24.2 C25.2 C32.2 C33.2 R25.2 R27.2 R28.2 R31.2 R34.2
NetD3_2: D3.2(A) R35.1
NetD4_2: D4.2(A) R60.2
NetD5_2: D5.2(A) R63.1
NetD6_2: D6.2(A) R66.2
NetD7_2: D7.2(A) R62.1
NetD8_2: D8.2(A) R61.2
NetD9_2: D9.2(A) R64.1
NetD10_2: D10.2(A) R65.2
NetD11_2: D11.2(A) R67.1
NetD12_2: D12.2(A) R68.2
NetD13_2: D13.2(A) R70.1
NetD14_2: D14.2(A) R71.2
NetQ1_8: Q1.8(GATE) R1.2 R35.2
NetQ2_8: Q2.8(GATE) R9.2 R63.2
NetQ3_8: Q3.8(GATE) R15.2 R62.2
NetQ4_8: Q4.8(GATE) R16.1 R61.1
NetQ5_8: Q5.8(GATE) R10.1 R66.1
NetQ6_8: Q6.8(GATE) R2.1 R60.1
NetQ7_8: Q7.8(GATE) R30.2 R64.2
NetQ8_8: Q8.8(GATE) R36.2 R67.2
NetQ9_8: Q9.8(GATE) R42.2 R70.2
NetQ10_8: Q10.8(GATE) R39.1 R71.1
NetQ11_8: Q11.8(GATE) R33.1 R68.1
NetQ12_8: Q12.8(GATE) R26.1 R65.1

Not connected (* = marked no-connect by the designer): U4 5(NC)*

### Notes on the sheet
- SR
- LDO: TPS71733
- Output Choke
- Temperature: TMP61
- ACL

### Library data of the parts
C6 C9 C20-C25 C32 C33 = CMP-0860440-1: CAP, CERM, 0.1 µF, 100 V,+/- 10%, X7R, AEC-Q200 Grade 1, 0805; Manufacturer: MuRata; SizeY_mm: 1.25; ValueDisplayed: 0.1µF; SizeX_mm: 2; Cap_Case: 0805; AEC Grade: 1; Polarized: N; Value: 0.1uF; TaMin_C: -55°C; SizeZ_mm: 1.45; TaMax_C: 125°C; U/M: EA; SizeArea_mm2: 2.5; AEC Qualified: Y; SizeAreaWB_mm2: 6.75; AEC Category: Q200
C12 C13 = CMP-0085818-1: as C7 on sheet Driver
C15 = CMP-0006324-2: CAP, CERM, 0.01 uF, 50 V, +/- 10%, X7R, AEC-Q200 Grade 1, 0402; Manufacturer: TDK; TaMin_C: -55°C; ESR_ohm: 0.3331; Polarized: N; SizeAreaWB_mm2: 3; Value1: 0.333065 ohm; U/M: EA; Value: 0.01uF; TaMax_C: 125°C; SizeZ_mm: 0.6; SizeX_mm: 1; SizeY_mm: 0.5; AEC Qualified: Y; Cap_F: 10nF; IRMS_A: 323.373mA; AEC Category: Q200
C19 C28 = CMP-0006319-2: CAP, CERM, 3300 pF, 50 V, +/- 10%, X7R, AEC-Q200 Grade 1, 0402; Manufacturer: TDK; TaMin_C: -55°C; ESR_ohm: 7.85178d; Polarized: N; SizeAreaWB_mm2: 3; Value1: 0.785178 ohm; U/M: EA; Value: 3300pF; TaMax_C: 125°C; SizeZ_mm: 0.6; SizeX_mm: 1; SizeY_mm: 0.5; AEC Qualified: Y; Cap_F: 3.3nF; IRMS_A: 2.72902dA; AEC Category: Q200
C30 C31 = CMP-0006356-1: as C1 on sheet Driver
D3-D14 = CMP-0028768-3: Diode, Schottky, 30 V, 0.2 A, AEC-Q101, SOD-523; Manufacturer: ON Semiconductor; SizeArea_mm2: 1.53; Vr_V: 30V; Green_Lifecycle: Not Set; Value2: 0.5V; Value1: 0.2A; AEC Qualified: Y; SizeY_mm: 0.9; AEC Category: Q101; SizeZ_mm: 0.65; Vf_V: 500mV; Io_A: 200mA; Green_REACh: Incomplete; SizeAreaWB_mm2: 5.13; TJmax_C: 125°C; Value: 30V; SizeX_mm: 1.7
J2 J3 = CMP-0055165-2: Standard Banana Jack, Uninsulated, 5.5mm; Manufacturer: Keystone; CT: TRUE; Green_REACh: Passed; CNHeader: FALSE; Green_Lifecycle: Active
J4 = CMP-0120912-1: Connector Unshrouded Header HDR 4 POS 1.27mm Solder RA Thru-Hole; Manufacturer: Samtec; ContactFinish: Gold,Nickel; Current_A: 3.4A; Row_Count: 2; AEC Qualified: No; Conn Gender: Male; Conn Orientation: Right Angle; SizeZ_mm: 3.56mm
Q1-Q12 = IAUTN06S5N008T: Insulated-Gate Field-Effect Transistor (IGFET), N-Channel, Enhancement, Body Diode, Pin 1 Source, 2 Source, 3 Source , 4 Source, 5 Source, 6 Source, 7 Source, 8 Gate, 9 Drain, 10 Drain, 11 Drain, 12 Drain, 13 Drain, 14 Drain, 15 Drain, 16 Drain, 16 Pins; Manufacturer: Infineon Technologies
Q13 Q14 = CMP-0077633-1: MOSFET, N-CH, 60 V, 287 A, AEC-Q101, DFN5 5x6mm; Manufacturer: ON Semiconductor; Alternate Manufacturer: None; ChType: N; QgTyp_nC: 52.0; SizeAreaWB_mm2: 58.2725; SizeArea_mm2: 31.6725; IdsMax_A: 287A; AEC Qualified: Y; VdsMax_V: 60V; Rdson45_ohm: 1.7m; Vgs_V: 20V; AEC Category: Q101; Value: 60V; SizeZ_mm: 1.0; SizeY_mm: 6.15; Value2: 52 nC; U/M: EA; Value1: 0.0017 ohm; SizeX_mm: 5.15
R1 R2 R9 R10 R15 R16 R26 R30 R33 R35 R36 R39 R42 R60-R68 R70 R71 = CMP-0081856-1: RES, 0, 0%, 0.2 W, AEC-Q200 Grade 0, 0402; Manufacturer: Vishay-Dale; SizeAreaWB_mm2: 3; SizeArea_mm2: 0.5; AEC Qualified: Y; AEC Category: Q200; Value: 0; SizeZ_mm: 0.6; Power_W: 200mW; VDC_V: 50V; Value2: 0.2W; SizeX_mm: 1
R3 R4 R22 R44 = CMP-0026754-1: RES, 10.0 k, 1%, 0.063 W, AEC-Q200 Grade 0, 0402; Manufacturer: Stackpole Electronics Inc; Power_W: 63mW; TempCo: 100 ppm/C; Value_Code: 10k0; U/M: EA; Value: 10.0k; EIA_Code: E96; Res_ohm: 10k; SizeX_mm: 1; SizeY_mm: 0.5; SizeZ_mm: 0.6; Value2: 0.063W; AEC Qualified: Y; VDC_V: 50V; AEC Grade: 0; AEC Category: Q200
R11 R14 R45 R54 = CMP-0078779-1: as R51 on sheet Driver
R17 R19 R20 R23 R25 R27 R28 R31 R32 R34 = CMP-0020442-3: RES, 0, 5%, 0.125 W, AEC-Q200 Grade 0, 0805; Manufacturer: Vishay-Dale; Power_W: 125mW; TempCo: 200 ppm/C; Value_Code: 0000; Value: 0; EIA_Code: E24; SizeX_mm: 2; SizeY_mm: 1.25; SizeZ_mm: 1.45; Value2: 0.125W; SizeArea_mm2: 2.5; AEC Qualified: Y; VDC_V: 150V; AEC Category: Q200
R29 R40 R41 R46 R47 R50 R56-R59 = CMP-0078924-1: RES, 0.0005, 1%, 3 W, AEC-Q200 Grade 0, 2512; Value_Code: M50; SizeArea_mm2: 20.16; AEC Qualified: Y; AEC Category: Q200; Res_ohm: 0.5m; Value: 0.0005; SizeZ_mm: 0.71; EIA_Code: E96; TempCo: 75 ppm/C; AEC Grade: 0; SizeY_mm: 3.2; Power_W: 1W; SizeX_mm: 6.3
RT1 RT2 = CMP-0120064-2: Automotive ±1% tolerance 10kΩ linear thermistor available in an 0402 package option 2-X1SON -40 to 125; Manufacturer: Texas Instruments; SizeZ_mm: 0.5mm; AEC Qualified: Yes; AEC Grade: Grade 1; Standoff Height: 0mm; TaMax_C: +125°C; TaMin_C: -40°C; AEC Category: Q200; CompType: IC
U4 = CMP-0082417-1: Low Noise, High-Bandwidth PSRR Low-Dropout 150mA Linear Regulator for Automotive Applications, DRV0006A (WSON-6); Alternate Manufacturer: Texas Instruments; SizeAreaWB_mm2: 9; SizeZ_mm: 0.8; SizeX_mm: 2; SizeArea_mm2: 4; CompType: IC; AEC Qualified: Y; AEC Category: Q200

## Sheet SR Card_Hardware.SchDoc
size 431 x 279 mm; Date: Not shown in title block; ApprovedBy: Not shown in title block; CheckedBy: Not shown in title block; Author: Not shown in title block; CompanyName: Not shown in title block; Engineer: Not shown in title block; Organization: Not shown in title block; Address1: Not shown in title block; Address2: Not shown in title block; Address3: Not shown in title block; Address4: Not shown in title block; DocumentNumber: 3; Revision: Use project parameter SCH_Rev; SheetNumber: 3; SheetTotal: 3; PageSetup: Record=PageOptions¦CenterHorizontal=True¦CenterVertical=True¦PrintScale=1.00¦XCorrection=1.00¦YCorrection=1.00¦PrintKind=0¦BorderSize=5000000¦LeftOffset=0¦BottomOffset=0¦Orientation=2¦PaperLength=1000¦PaperWidth=1000¦Scale=100¦PaperSource=15¦PrintQuality=600¦MediaType=1¦DitherType=10¦PaperKind=Letter¦PrintScaleMode=1
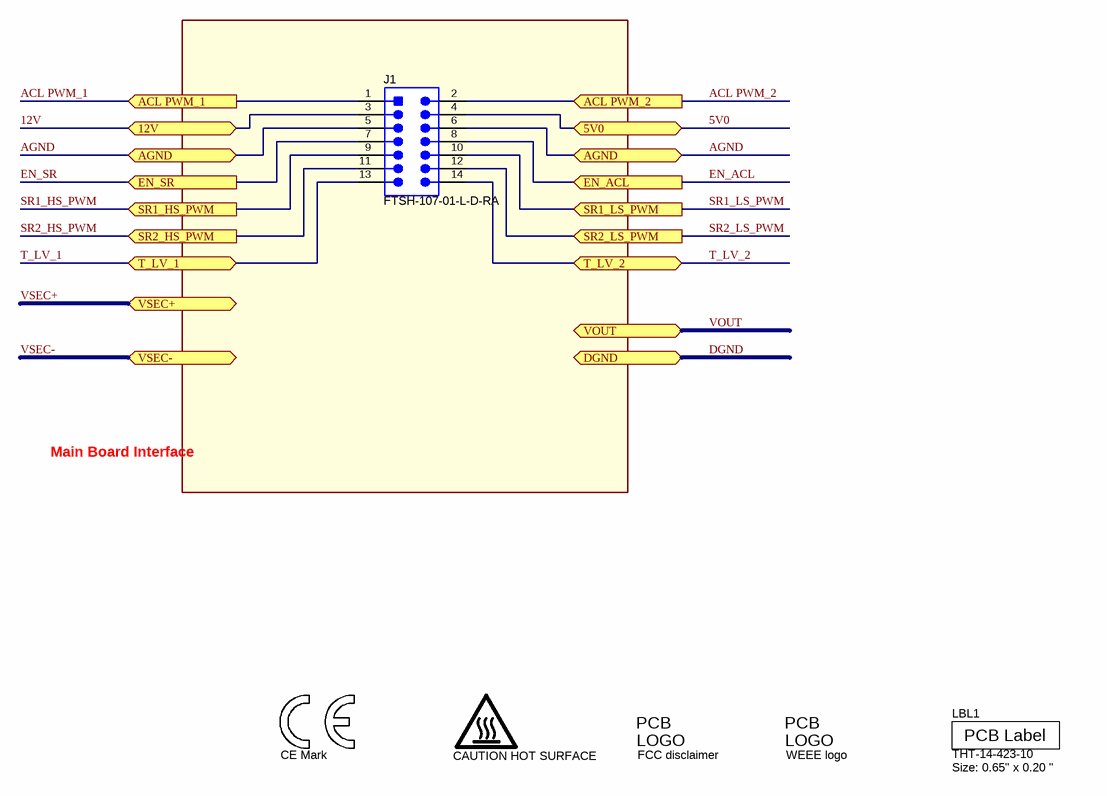
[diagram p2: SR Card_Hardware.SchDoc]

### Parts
CAUTION_HOT_SURFACE1  CAUTION HOT SURFACE  [IEC_HotSurface_Small]  (no BOM)
J1  FTSH-107-01-L-D-RA  [Samtec_FTSH-107-01-L-D-RA]
LBL1  THT-14-423-10  Note: Size: 0.65" x 0.20 "  [Label_650x200]
Logo1  CE Mark  [CE_Mark_5mm]  (no BOM)
Logo2  FCC disclaimer  [FCC_disclaimer]  (no BOM)
Logo3  WEEE logo  [WEEE_Minimum]  (no BOM)

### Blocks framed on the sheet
Main Board Interface: J1

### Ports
5V0 (bidir), 12V (bidir), ACL PWM_1 (in), ACL PWM_2 (in), AGND (bidir), DGND (bidir), EN_ACL (in), EN_SR (in), SR1_HS_PWM (in), SR1_LS_PWM (in), SR2_HS_PWM (in), SR2_LS_PWM (in), T_LV_1 (bidir), T_LV_2 (bidir), VOUT (bidir), VSEC+ (bidir), VSEC- (bidir)

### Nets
12V: J1.3 ; port 12V
AGND: J1.5 J1.6 ; port AGND
5V0: J1.4 ; port 5V0
ACL PWM_1: J1.1 ; port ACL PWM_1
ACL PWM_2: J1.2 ; port ACL PWM_2
EN_ACL: J1.8 ; port EN_ACL
EN_SR: J1.7 ; port EN_SR
SR1_HS_PWM: J1.9 ; port SR1_HS_PWM
SR1_LS_PWM: J1.10 ; port SR1_LS_PWM
SR2_HS_PWM: J1.11 ; port SR2_HS_PWM
SR2_LS_PWM: J1.12 ; port SR2_LS_PWM
T_LV_1: J1.13 ; port T_LV_1
T_LV_2: J1.14 ; port T_LV_2

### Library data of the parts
CAUTION_HOT_SURFACE1 = CMP-0074837-1: IEC 61010-1 Hot Surface Warning; Library Reference: IEC_HotSurface; SymbolCreator: a0412235
J1 = CMP-0056012-2: Header, 50mil, 7x2, R/A, TH; Manufacturer: Samtec
LBL1 = CMP-0003625-1: Thermal Transfer Printable Labels, 0.650" W x 0.200" H - 10,000 per roll; Manufacturer: Brady; CompType: Label
Logo1 = CMP-0074844-1: SymbolCreator: a0412235
Logo2 = CMP-0074847-1: FCC_disclaimer; Library Reference: Logo
Logo3 = CMP-0074769-1

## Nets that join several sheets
3V3: Driver (R6.2 R8.2 R38.2), Power Stage (6 pins)
12V: Driver (10 pins), SR Card_Hardware (J1.3)
AGND: Driver (14 pins), Power Stage (11 pins), SR Card_Hardware (J1.5 J1.6)
DGND: Driver (10 pins), Power Stage (55 pins)
5V0: Power Stage (C12.1 U4.4 U4.6), SR Card_Hardware (J1.4)
ACL PWM_1: Driver (R52.1), SR Card_Hardware (J1.1)
ACL PWM_2: Driver (R55.1), SR Card_Hardware (J1.2)
ACL_G1: Driver (R18.2), Power Stage (Q13.4 R3.2)
ACL_G2: Driver (R37.2), Power Stage (Q14.4 R4.2)
EN_ACL: Driver (R43.1), SR Card_Hardware (J1.8)
EN_SR: Driver (R13.1 R24.1), SR Card_Hardware (J1.7)
SR1 HO: Driver (U1.6 U1.7), Power Stage (7 pins)
SR1 LO: Driver (U3.6 U3.7), Power Stage (7 pins)
SR1_HS_PWM: Driver (R48.1), SR Card_Hardware (J1.9)
SR1_LS_PWM: Driver (R12.1), SR Card_Hardware (J1.10)
SR2 HO: Driver (U6.6 U6.7), Power Stage (7 pins)
SR2 LO: Driver (U8.6 U8.7), Power Stage (7 pins)
SR2_HS_PWM: Driver (R49.1), SR Card_Hardware (J1.11)
SR2_LS_PWM: Driver (R53.1), SR Card_Hardware (J1.12)
T_LV_1: Power Stage (C28.1 R44.1 RT1.2), SR Card_Hardware (J1.13)
T_LV_2: Power Stage (C19.1 R22.1 RT2.2), SR Card_Hardware (J1.14)
VSEC+: Driver (10 pins), Power Stage (50 pins)
VSEC-: Driver (10 pins), Power Stage (50 pins)

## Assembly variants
PMP41147 SR Card: not fitted J2 J3 Q1 Q5 Q9 Q12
